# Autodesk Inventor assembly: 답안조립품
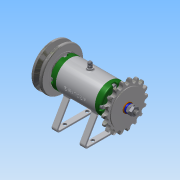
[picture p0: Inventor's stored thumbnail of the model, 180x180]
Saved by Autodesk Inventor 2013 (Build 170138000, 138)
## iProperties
Created: 2016-03
Part Number: 답안조립품
Document SubType Name: Assembly
Designer: Administrator
Author: Administrator
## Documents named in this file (16)
- C:\Users\Administrator\Desktop\460308V1028\답안조립품.iam
- C:\Users\Administrator\Desktop\460308V1028\본체.ipt
- C:\Users\Administrator\Desktop\460308V1028\베어링 15 x 32 x 9.ipt
- C:\Users\Administrator\Desktop\460308V1028\축.ipt
- C:\Users\Administrator\Desktop\460308V1028\커버.ipt
- C:\Users\Administrator\Desktop\460308V1028\볼트 M4 x 12.ipt
- C:\Users\Administrator\Desktop\460308V1028\오일 실 15 25 7.ipt
- C:\Users\Administrator\Desktop\460308V1028\키 3 x 3 x 12.ipt
- C:\Users\Administrator\Desktop\460308V1028\스프로킷.ipt
- C:\Users\Administrator\Desktop\460308V1028\와셔 8x17.ipt
- C:\Users\Administrator\Desktop\460308V1028\스프링와셔 8.ipt
- C:\Users\Administrator\Desktop\460308V1028\너트 M 8.ipt
- C:\Users\Administrator\Desktop\460308V1028\V벨트풀리.ipt
- C:\Users\Administrator\Desktop\460308V1028\니플 M 6 x 0.75.ipt
- C:\Users\Administrator\Desktop\460308V1028\와셔 6x11.5.ipt
- C:\Users\Administrator\Desktop\460308V1028\볼트 M 6 x 8.ipt
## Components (11 placed, 3 different names)
1. KS B 2023 6002 - 15 x 32 x 9:1
2. KS B 2023 6002 - 15 x 32 x 9:2
3. V벨트풀리:1 — 각도:4
4. ISO 4762 M4 x 12:2
5. ISO 4762 M4 x 12:3
6. ISO 4762 M4 x 12:4
7. ISO 4762 M4 x 12:5
8. ISO 4762 M4 x 12:1
9. ISO 4762 M4 x 12:6
10. ISO 4762 M4 x 12:7
11. ISO 4762 M4 x 12:8
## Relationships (1: Angle 1)
- 각도:4 [Angle]: V벨트풀리:1
